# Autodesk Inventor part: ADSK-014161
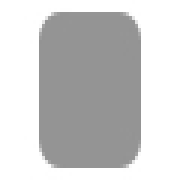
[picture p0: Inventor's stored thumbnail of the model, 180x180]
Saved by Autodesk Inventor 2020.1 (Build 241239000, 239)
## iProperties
Created: 2019-01
Part Number: ADSK-014161
Material: Stahl, weich
Document SubType Name: Modeling
Designer: lutzd
Language: de-DE
Size Designation: 5 x 39,384472 x 39,384472
Categories: <MemberInstance><Categories><Category DisplayName="Sonstige Bauteile" InternalName="5aa15e00-363f-49f2-933f-16f664388e3f" Mnemonic="OTHER"><Category DisplayName
Mass: 60.0398 g
Surface Area: 38.0412 cm^2
Volume: 7.64838 cm^3
Density: 7.85 g/cm^3
Appearance: Halbpoliert
IsCustomPart: 1
Title: end cap
Author: lutzd
Revision Number: -
Dimensions: 39,4x39,4x5 mm
Mass: 0,06 kg
DocNumber: ADSK-014161
Folder: 01 - Themengebiete\Simplification\01 - Packaging machine\
VDS_Category: 3D Komponenten
VDS_NumSchm: Autodesk
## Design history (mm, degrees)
sketch "Sketch1"
  geometry: L1 (0, 20.175)-(0, -21.446); L2 (-20.203, 0)-(20.169, 0); L3 (-19.692, 19.692)-(19.692, 19.692); L4 (19.692, 19.692)-(19.692, -19.692); L5 (19.692, -19.692)-(-19.692, -19.692); L6 (-19.692, -19.692)-(-19.692, 19.692); 1 further point
  constraints: 12 end point, 2 horizontal, 2 parallel, 2 point on line, 1 perpendicular, 1 vertical
  dimensions: "d0" = 39.38447 distance between parallel lines of L5 L3 (= height); "d1" = 19.69224 distance between parallel lines of L2 L3 (= 0.5 x height); "d2" = 39.38447 distance between parallel lines of L6 L4 (= width); "d3" = 19.69224 distance between parallel lines of L6 L1 (= 0.5 x width)
extrude "Extrusion1" new body sketch "Sketch1" distance "d4" = 5 (= thickness); taper "d5" = 0 deg
fillet "Fillet1" dims "d6" = 5 (= fillet), "d7" = 0, "fillet" = 5 [user parameter; used in 1 equation term]
chamfer "Chamfer1" distance "d8" = 0 (computed from chamfer); stored, may be unused: second distance "d9" = 2, angle "d10" = 45 deg; dims "d11" = 0, "chamfer" = 0 [user parameter; used in 1 equation term]
body "Solid1"
other parameters: "thickness" = 5 [user parameter; used in 1 equation term], "width" = 39.38447 [user parameter; used in 2 equation terms], "height" = 39.38447 [user parameter; used in 2 equation terms]
